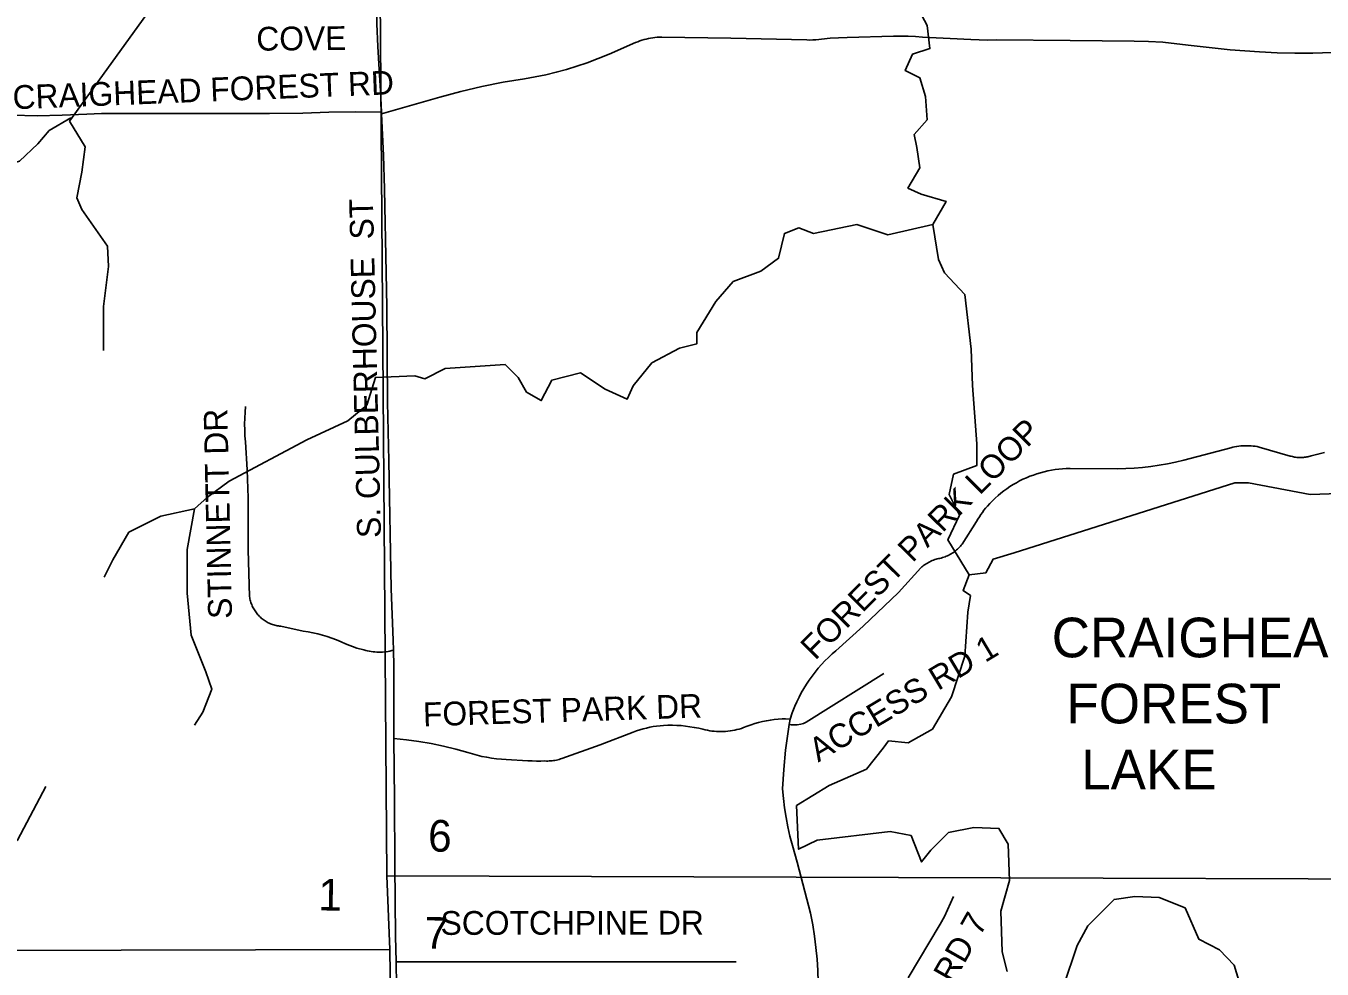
# Model space of a CAD drawing. Extents: x 1670563 to 1761545, y 515755 to 578944.
# Drawn here: x 1692585 to 1696673, y 528045 to 531020 of the extents above; entities that cross this region are included whole.
import ezdxf

# ---------------------------------------------------------------- set-up
doc = ezdxf.new("R2010")
doc.units = 0
for name, color, linetype in [('4_TwnRge', 7, 'Continuous'), ('5_sectionlines', 7, 'Continuous'), ('62_text', 7, 'Continuous'), ('SHP_LINE', 7, 'Continuous'), ('STREETCL', 7, 'Continuous'), ('STRNAMES', 7, 'Continuous')]:
    doc.layers.add(name, color=color, linetype=linetype)

msp = doc.modelspace()

# ---------------------------------------------------------------- linework, layer by layer
at = {"layer": '4_TwnRge'}
msp.add_lwpolyline([(1693900.8, 565154.5), (1693867.8, 559919.3), (1693819.4, 554617.2), (1693735.2, 549363.2), (1693687.1, 544103.2), (1693620.9, 538819.1), (1693684.6, 533590.9), (1693722.5, 528338.7), (1693732, 528106.5), (1693805.9, 522944.4), (1693926.3, 517684.2)], dxfattribs=at)
at = {"layer": '5_sectionlines'}
for points in [[(1693722.5, 528338.7), (1698889.2, 528322.1), (1704145.7, 528359.3), (1709496, 528430.4), (1714842.3, 528473.5)], [(1683015, 528116), (1688224.2, 528093.7), (1693732, 528106.5)]]:
    msp.add_lwpolyline(points, dxfattribs=at)
at = {"layer": 'SHP_LINE'}
for points in [[(1692722, 530719), (1693204, 531387), (1693253, 531449), (1693260, 531533), (1693227, 531732)], [(1695445, 530393), (1695487, 530466), (1695409, 530489), (1695367, 530508), (1695404, 530572), (1695395, 530636), (1695386, 530677), (1695427, 530723), (1695422, 530797), (1695404, 530856), (1695358, 530879), (1695381, 530930), (1695436, 530948), (1695427, 531021), (1695367, 531136), (1695340, 531251), (1695321, 531255)], [(1692726, 530730), (1692658, 530690), (1692622, 530648), (1692564, 530593), (1692464, 530564), (1692396, 530499), (1692354, 530416), (1692328, 530341), (1692351, 530287), (1692348, 530238), (1692270, 530090)], [(1692722, 530719), (1692771, 530638), (1692761, 530558), (1692745, 530477), (1692761, 530441), (1692842, 530325), (1692845, 530261), (1692829, 530135), (1692829, 529996)], [(1695445, 530393), (1695303, 530361), (1695206, 530393), (1695069, 530365), (1695023, 530383), (1694977, 530365), (1694959, 530287), (1694903, 530246), (1694816, 530214), (1694761, 530150), (1694701, 530053), (1694701, 530017), (1694646, 530003), (1694559, 529957), (1694500, 529884), (1694481, 529842), (1694412, 529874), (1694334, 529925), (1694243, 529902), (1694210, 529838), (1694164, 529865), (1694137, 529911), (1694096, 529952), (1693907, 529939), (1693843, 529907), (1693811, 529916), (1693687, 529911), (1693660, 529824), (1693600, 529774), (1693471, 529714), (1693226, 529584), (1693157, 529533), (1693116, 529497)], [(1695560, 529288), (1695493, 529399), (1695529, 529477), (1695497, 529542), (1695511, 529606), (1695584, 529633), (1695584, 529702), (1695571, 529886), (1695566, 530000), (1695546, 530173), (1695482, 530241), (1695463, 530283), (1695445, 530393)], [(1695680, 528037), (1695664, 528100), (1695660, 528228), (1695687, 528324), (1695683, 528439), (1695654, 528489), (1695575, 528492), (1695495, 528476), (1695439, 528420), (1695410, 528383), (1695377, 528466), (1695311, 528479), (1695081, 528452), (1695022, 528423), (1695015, 528561), (1695118, 528624), (1695236, 528676), (1695289, 528742), (1695306, 528765), (1695368, 528759), (1695444, 528802), (1695504, 528904), (1695546, 529032), (1695556, 529171), (1695564, 529223), (1695541, 529239), (1695560, 529288), (1695613, 529295), (1695636, 529338), (1695702, 529358), (1696398, 529579), (1696441, 529579), (1696636, 529542), (1696726, 529545)], [(1693116, 529497), (1693010, 529474), (1692909, 529423), (1692859, 529336), (1692831, 529281)], [(1693116, 529497), (1693093, 529368), (1693093, 529231), (1693106, 529098), (1693152, 528983), (1693171, 528928), (1693143, 528855), (1693116, 528814)], [(1692647, 528621), (1692558, 528452), (1692428, 528328), (1692366, 528269), (1692330, 528242), (1692241, 528177), (1692120, 528170), (1692014, 528164), (1691838, 528178), (1691563, 528183), (1691535, 528189)], [(1696426, 527958), (1696396, 528057), (1696350, 528106), (1696284, 528139), (1696241, 528238), (1696159, 528271), (1696083, 528274), (1696017, 528265), (1695934, 528182), (1695901, 528120), (1695858, 527991)]]:
    msp.add_lwpolyline(points, dxfattribs=at)
at = {"layer": 'STREETCL'}
for points in [[(1693691.3, 531047.1), (1693691.8, 531026.4), (1693694.4, 530954.4), (1693698.4, 530882.5), (1693703.2, 530813.8), (1693706.1, 530747.1)], [(1693706.3, 530742.4), (1693890.7, 530795.2), (1693956.5, 530812.9), (1694023, 530828.4), (1694089.9, 530841.8), (1694157.2, 530853), (1694190.7, 530858.6), (1694224.1, 530865.3), (1694257.2, 530873.2), (1694290, 530882.2), (1694322.4, 530892.4), (1694354.5, 530903.6), (1694424.1, 530930.7), (1694507.8, 530967), (1694514.3, 530969.7), (1694520.9, 530972.2), (1694527.6, 530974.4), (1694534.3, 530976.4), (1694541.1, 530978.2), (1694548, 530979.8), (1694554.9, 530981.1), (1694561.9, 530982.2), (1694568.9, 530983), (1694575.9, 530983.6), (1694582.9, 530984), (1694590, 530984.1), (1694808.6, 530980.5), (1695047.6, 530975.2), (1695057.1, 530975.1), (1695066.5, 530975.4), (1695075.9, 530975.9), (1695085.3, 530976.7), (1695094.6, 530977.9), (1695121.4, 530980.4), (1695148.2, 530982.2), (1695175, 530983.3), (1695321, 530987.1), (1695344.1, 530987.3), (1695367.1, 530987), (1695390.2, 530986), (1695413.2, 530984.4), (1695564.9, 530976.2), (1695591.9, 530975.2), (1695618.9, 530974.9), (1695645.9, 530975.4), (1695879, 530973.6), (1696080.2, 530971.8), (1696125.3, 530970.6), (1696170.4, 530967.8), (1696215.3, 530963.4), (1696260, 530957.4), (1696382.9, 530943.8), (1696475.6, 530937.5), (1696531.5, 530934.5), (1696587.6, 530933.3), (1696643.6, 530933.9), (1696767.4, 530937.5)], [(1692532.5, 530737.9), (1692541, 530737.6), (1692619.7, 530736.4), (1692698.4, 530737.6), (1692777.1, 530741.1), (1692823.1, 530743.2), (1692869.2, 530743.8), (1692915.2, 530742.9), (1693236.9, 530743.8), (1693353.2, 530743.8), (1693457.8, 530744.7), (1693540.5, 530747.8), (1693623.3, 530748.6), (1693706.1, 530747.1)], [(1693706.1, 530747.1), (1693706.3, 530742.4)], [(1693706.3, 530742.4), (1693712.1, 530610.4), (1693715.7, 530505.8), (1693716.8, 530450), (1693719.4, 530294.8), (1693723.1, 530133.3), (1693723.8, 529983.2), (1693725.6, 529833.5), (1693728.9, 529648.1), (1693736.7, 529244.1), (1693742.9, 529082.6), (1693744.4, 529050.8)], [(1693744.4, 529050.8), (1693738.7, 529049.4), (1693732.9, 529048.1), (1693727, 529047), (1693721.1, 529046.1), (1693715.2, 529045.4), (1693709.3, 529045), (1693703.4, 529044.7), (1693697.4, 529044.7), (1693691.5, 529044.8), (1693685.5, 529045.2), (1693679.6, 529045.8), (1693673.7, 529046.5), (1693667.9, 529047.5), (1693662, 529048.7), (1693656.3, 529050.1), (1693650.5, 529051.6), (1693628.9, 529057.1), (1693592.6, 529071.1), (1693578.5, 529077.6), (1693564.1, 529083.6), (1693549.6, 529089), (1693534.9, 529094), (1693520, 529098.4), (1693505, 529102.3), (1693489.8, 529105.7), (1693474.6, 529108.6), (1693459.2, 529110.9), (1693388.3, 529126.2), (1693384.5, 529126.7), (1693380.8, 529127.2), (1693377.1, 529127.9), (1693373.5, 529128.6), (1693369.8, 529129.6), (1693366.2, 529130.6), (1693362.7, 529131.8), (1693359.1, 529133), (1693355.6, 529134.4), (1693352.2, 529136), (1693348.8, 529137.6), (1693345.5, 529139.4), (1693342.3, 529141.2), (1693339.1, 529143.2), (1693335.9, 529145.3), (1693332.9, 529147.5), (1693329.9, 529149.8), (1693327, 529152.2), (1693324.2, 529154.6), (1693321.5, 529157.2), (1693318.9, 529159.9), (1693316.3, 529162.7), (1693313.9, 529165.5), (1693311.6, 529168.5), (1693309.3, 529171.5), (1693307.2, 529174.6), (1693305.2, 529177.7), (1693303.2, 529180.9), (1693301.4, 529184.2), (1693299.7, 529187.6), (1693298.2, 529191), (1693296.7, 529194.4), (1693295.3, 529197.9), (1693294.1, 529201.5), (1693293, 529205.1), (1693292.1, 529208.7), (1693291.2, 529212.4), (1693290.5, 529216), (1693289.9, 529219.8), (1693285.7, 529367.1), (1693285.1, 529531.7), (1693282.2, 529620), (1693276.9, 529708.2), (1693275.5, 529726.8), (1693274.7, 529745.4), (1693274.5, 529764), (1693274.9, 529782.6), (1693275.9, 529801.2), (1693277.5, 529819.8)], [(1694995.2, 528832.8), (1695001.5, 528853), (1695010.1, 528873.9), (1695016.4, 528888.3), (1695023.2, 528902.5), (1695030.5, 528916.4), (1695038.3, 528930), (1695046.6, 528943.4), (1695055.3, 528956.5), (1695064.4, 528969.3), (1695074, 528981.8), (1695084, 528993.9), (1695094.4, 529005.7), (1695105.1, 529017.1), (1695116.3, 529028.2), (1695127.9, 529038.8), (1695139.8, 529049.1), (1695226.1, 529126.5), (1695336.7, 529232.9), (1695407.6, 529310.5), (1695410.8, 529313.3), (1695414.1, 529316), (1695417.5, 529318.5), (1695421, 529321), (1695424.6, 529323.3), (1695428.2, 529325.6), (1695431.9, 529327.7), (1695435.7, 529329.6), (1695439.5, 529331.5), (1695443.4, 529333.2), (1695447.3, 529334.8), (1695451.3, 529336.3), (1695455.4, 529337.6), (1695459.4, 529338.8), (1695463.6, 529339.5), (1695467.8, 529340.4), (1695471.9, 529341.4), (1695476, 529342.6), (1695480, 529343.9), (1695484, 529345.3), (1695487.9, 529346.9), (1695491.8, 529348.6), (1695495.6, 529350.4), (1695499.4, 529352.4), (1695503.1, 529354.5), (1695506.7, 529356.7), (1695510.2, 529359.1), (1695513.7, 529361.5), (1695517, 529364.1), (1695520.3, 529366.8), (1695523.5, 529369.7), (1695526.5, 529372.6), (1695529.5, 529375.6), (1695532.4, 529378.7), (1695535.1, 529382), (1695537.8, 529385.3), (1695583.5, 529457), (1695587.7, 529464.4), (1695592.1, 529471.5), (1695596.7, 529478.6), (1695601.6, 529485.4), (1695606.7, 529492.1), (1695612, 529498.6), (1695617.6, 529505), (1695625.5, 529513.7), (1695633.7, 529522.1), (1695642.3, 529530.3), (1695651, 529538.2), (1695660.1, 529545.8), (1695669.4, 529553), (1695678.9, 529560), (1695688.7, 529566.6), (1695698.7, 529572.9), (1695708.9, 529578.9), (1695719.2, 529584.5), (1695729.8, 529589.7), (1695740.5, 529594.6), (1695751.4, 529599.2), (1695762.5, 529603.3), (1695773.7, 529607.1), (1695784.9, 529610.5), (1695796.4, 529613.6), (1695807.9, 529616.2), (1695819.4, 529618.4), (1695831.1, 529620.3), (1695842.8, 529621.8), (1695854.6, 529622.8), (1695866.3, 529623.5), (1695878.1, 529623.8), (1696027.7, 529622.9), (1696054.1, 529623.5), (1696080.5, 529624.8), (1696106.9, 529627.1), (1696133.2, 529630.1), (1696159.3, 529634), (1696185.4, 529638.6), (1696211.3, 529644.1), (1696236.9, 529650.4), (1696384.9, 529689.3), (1696391.2, 529690.9), (1696397.5, 529692.2), (1696403.9, 529693.4), (1696410.3, 529694.3), (1696416.7, 529695), (1696423.2, 529695.5), (1696429.7, 529695.7), (1696436.1, 529695.8), (1696442.6, 529695.6), (1696449.1, 529695.2), (1696455.5, 529694.7), (1696462, 529693.8), (1696468.4, 529692.8), (1696474.7, 529691.6), (1696572.7, 529663.2), (1696576.1, 529662.2), (1696579.5, 529661.3), (1696582.9, 529660.5), (1696586.4, 529659.8), (1696589.9, 529659.3), (1696593.4, 529658.9), (1696596.9, 529658.6), (1696600.4, 529658.4), (1696603.9, 529658.3), (1696607.4, 529658.3), (1696611, 529658.5), (1696614.5, 529658.8), (1696618, 529659.2), (1696621.5, 529659.7), (1696624.9, 529660.3), (1696628.4, 529661), (1696631.8, 529661.9), (1696635.2, 529662.8), (1696638.5, 529663.9), (1696660, 529668.7), (1696681.3, 529674.2)], [(1693744.4, 529050.8), (1693745.5, 529001.5), (1693745.5, 528784.1), (1693745.6, 528772)], [(1695290.3, 528977.4), (1695045.3, 528824.1), (1695037.6, 528820), (1695028.5, 528817.3), (1695017.4, 528815.4), (1695008.3, 528815), (1694999, 528815.6), (1694991.9, 528816.4)], [(1693745.6, 528772), (1693785, 528768.1), (1693824.1, 528762.8), (1693863.1, 528756.1), (1693901.8, 528748.1), (1693940.2, 528738.7), (1693978.3, 528728), (1693993.1, 528723.5), (1694008, 528719.5), (1694023.1, 528716), (1694038.3, 528713), (1694053.6, 528710.6), (1694069, 528708.7), (1694084.4, 528707.4), (1694099.9, 528706.6), (1694168.2, 528702.1), (1694181.5, 528701.4), (1694194.9, 528701.1), (1694208.3, 528701.1), (1694221.7, 528701.5), (1694226.3, 528701.3), (1694230.8, 528701.3), (1694235.4, 528701.4), (1694239.9, 528701.7), (1694244.5, 528702.1), (1694249, 528702.6), (1694253.5, 528703.4), (1694257.9, 528704.2), (1694262.4, 528705.2), (1694266.8, 528706.4), (1694271.2, 528707.7), (1694275.5, 528709.1), (1694395.5, 528752.4), (1694499.9, 528792.1), (1694510.2, 528796), (1694520.6, 528799.5), (1694531.1, 528802.7), (1694541.7, 528805.4), (1694552.5, 528807.8), (1694563.3, 528809.8), (1694574.1, 528811.5), (1694585, 528812.7), (1694596, 528813.6), (1694609.9, 528814.1), (1694623.8, 528814.1), (1694637.8, 528813.7), (1694651.6, 528812.8), (1694665.5, 528811.5), (1694679.3, 528809.6), (1694693, 528807.4), (1694706.7, 528804.6), (1694720.2, 528801.5), (1694727.3, 528799.7), (1694734.3, 528798.2), (1694741.4, 528796.9), (1694748.6, 528795.9), (1694755.7, 528795.1), (1694762.9, 528794.5), (1694770.2, 528794.2), (1694777.4, 528794.1), (1694784.6, 528794.3), (1694791.8, 528794.7), (1694799, 528795.4), (1694806.2, 528796.2), (1694813.3, 528797.4), (1694820.4, 528798.7), (1694827.5, 528800.3), (1694834.4, 528802.2), (1694841.4, 528804.2), (1694848.2, 528806.5), (1694859.9, 528811.1), (1694871.8, 528815.4), (1694883.8, 528819.2), (1694895.9, 528822.6), (1694908.1, 528825.6), (1694920.5, 528828.2), (1694932.9, 528830.4), (1694945.3, 528832.2), (1694957.8, 528833.5), (1694970.4, 528834.5), (1694980.3, 528834.5), (1694995.2, 528832.8)], [(1695083.7, 528003.8), (1695082.5, 528040.3), (1695080.2, 528076.7), (1695076.8, 528113), (1695072.3, 528149.1), (1695066.7, 528185.2), (1695060, 528221), (1695017.5, 528382.3), (1695002.6, 528435.4), (1694994.8, 528464.6), (1694988.1, 528494), (1694982.4, 528523.7), (1694977.7, 528553.5), (1694974.1, 528583.4), (1694971.5, 528613.5), (1694974.9, 528674.7), (1694980.3, 528735.8), (1694991.9, 528816.4)], [(1694991.9, 528816.4), (1694995.2, 528832.8)], [(1693745.6, 528772), (1693747.3, 528580), (1693748.5, 528373.9), (1693750.7, 528149.2), (1693752.2, 528068.1)], [(1695368, 528017.1), (1695468.6, 528187.1), (1695482.1, 528211.4), (1695510.5, 528274.2)], [(1694825.1, 528068.1), (1693752.2, 528068.1)], [(1693752.2, 528068.1), (1693753.6, 527992.8), (1693754.6, 527985.6), (1693757.7, 527755.8), (1693760.8, 527633.5), (1693761.7, 527562.8)]]:
    msp.add_lwpolyline(points, dxfattribs=at)

# ---------------------------------------------------------------- texts
at = {"layer": '62_text'}
for s, p in [('6', (1693852.4, 528416.2)), ('1', (1693506.3, 528230.4)), ('7', (1693841.5, 528109.8))]:
    msp.add_text(s, height=100, rotation=358.9337, dxfattribs=at).set_placement(p)
at = {"layer": 'SHP_LINE'}
for s, p in [('CRAIGHEAD', (1695820.4, 529028.3)), (' FOREST', (1695820.4, 528820)), ('  LAKE', (1695820.4, 528611.6))]:
    msp.add_text(s, height=125, dxfattribs=at).set_placement(p)
at = {"layer": 'STRNAMES'}
for s, rotation, p in [(' COVE', 0.4952, (1693283.7, 530941.2)), ('CRAIGHEAD FOREST RD', 2.2662, (1692543.9, 530756.6)), ('S. CULBERHOUSE  ST', 91.3694, (1693704.7, 529405.5)), ('STINNETT DR', 91.2879, (1693234.8, 529150.3)), ('FOREST PARK LOOP', 45.0525, (1695073.9, 529016.9)), ('ACCESS RD 1', 30.8343, (1695083.9, 528696.1)), ('FOREST PARK DR', 1.8124, (1693838.2, 528810.6)), ('SCOTCHPINE DR', 0.0824, (1693892.7, 528153)), ('ACCESS RD 7', 60.3465, (1695290.7, 527613.7))]:
    msp.add_text(s, height=75, rotation=rotation, dxfattribs=at).set_placement(p)

doc.saveas('drawing.dxf')
